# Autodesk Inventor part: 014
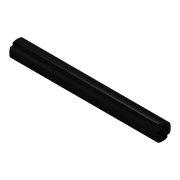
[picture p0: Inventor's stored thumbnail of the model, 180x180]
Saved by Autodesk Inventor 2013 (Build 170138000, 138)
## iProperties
Created: 2013-02
Part Number: 014
Material: Generic
Document SubType Name: Modeling
Designer: perblt
Density: 1 g/cm^3
Author: perblt
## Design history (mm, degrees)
sketch "Sketch1"
  geometry: L1 (1, -2.182)-(-1, -2.182); L2 (-1, 2.182)-(1, 2.182); L3 (1, -2.182)-(-1, 2.182); L4 (-1, -2.182)-(1, 2.182); L5 (-2.182, -1)-(-2.182, 1); L6 (2.182, 1)-(2.182, -1); L7 (2.182, -1)-(-2.182, 1); L8 (-2.182, -1)-(2.182, 1); L9 (2.182, -1)-(1, -1); L10 (-1, -1)-(-2.182, -1); L11 (1, 2.182)-(1, 1); L12 (1, -1)-(1, -2.182); L13 (-2.182, 1)-(-1, 1); L14 (1, 1)-(2.182, 1); L15 (-1, -2.182)-(-1, -1); L16 (-1, 1)-(-1, 2.182); A1 r 2.4 centre (0, 0) between (-1, -2.182) and (1, -2.182); A2 r 2.4 centre (0, 0) between (2.182, -1) and (2.182, 1); A3 r 2.4 centre (0, 0) between (1, 2.182) and (-1, 2.182); A4 r 2.4 centre (0, 0) between (-2.182, 1) and (-2.182, -1); 1 further point
  constraints: 32 end point, 10 parallel, 8 point on circle, 4 centre point, 4 midpoint, 4 perpendicular, 3 horizontal, 1 coincident
  dimensions: "d1" = 2 distance of L2.start L2.end; "d2" = 2 distance of L5.start L5.end
extrude "Extrusion1" new body sketch "Sketch1" distance "d3" = 40; taper "d4" = 0 deg
chamfer "Chamfer1" distance "d5" = 0.5; stored, may be unused: second distance "d6" = 2, angle "d7" = 45 deg
chamfer "Chamfer2" distance "d8" = 0.5; stored, may be unused: second distance "d9" = 2, angle "d10" = 45 deg
chamfer "Chamfer3" distance "d11" = 0.1; stored, may be unused: second distance "d12" = 2, angle "d13" = 45 deg
body "Solid1"
other parameters: "d0" = 4.8
